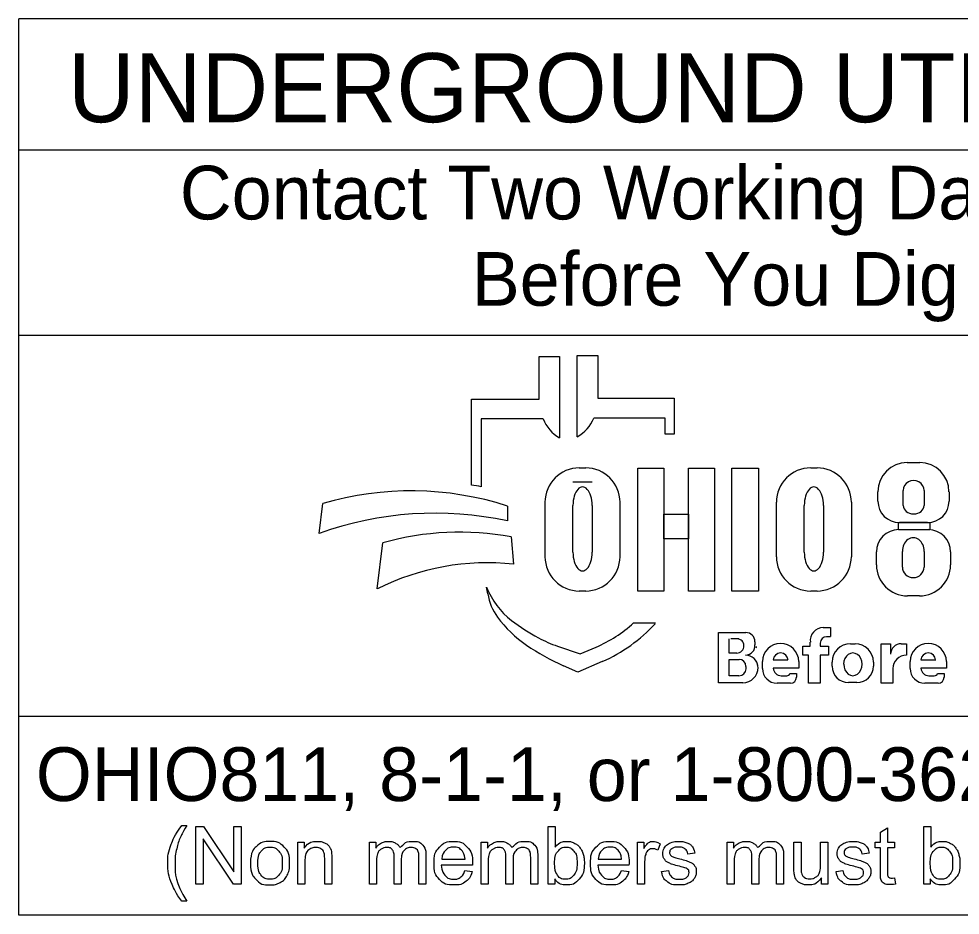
# Model space of a CAD drawing. Extents: x 0 to 34, y 0 to 22.
# Drawn here: x 2.378 to 4.831, y 2.661 to 4.999 of the extents above; entities that cross this region are included whole.
import ezdxf

# ---------------------------------------------------------------- set-up
doc = ezdxf.new("R2010")
doc.units = 0
doc.layers.add('SH_Data', color=7, linetype='Continuous')
doc.layers.add('SH_Text', color=7, linetype='Continuous')

msp = doc.modelspace()

# ---------------------------------------------------------------- linework, layer by layer
at = {"layer": 'SH_Data'}
for p, q in [((2.3775, 2.6613), (2.3775, 4.9988)), ((6.6275, 4.9988), (2.3775, 4.9988)), ((2.3775, 4.6573), (6.6275, 4.6573)), ((2.3775, 4.1739), (6.6275, 4.1739)), ((6.6275, 3.1792), (2.3775, 3.1792)), ((6.6275, 2.6613), (2.3775, 2.6613))]:
    msp.add_line(p, q, dxfattribs=at)
at = {"layer": 'SH_Text'}
for p, q in [((3.7335, 4.0068), (3.7335, 4.1183)), ((3.7335, 4.1183), (3.7872, 4.1183)), ((3.7872, 4.1183), (3.7872, 3.9062)), ((3.8329, 3.9086), (3.8329, 4.1206)), ((3.8329, 4.1206), (3.8865, 4.1206)), ((3.8865, 4.1206), (3.8865, 4.0092)), ((3.5576, 3.7829), (3.5576, 4.0068)), ((3.5576, 4.0068), (3.7335, 4.0068)), ((3.8865, 4.0092), (4.0857, 4.0092)), ((4.0857, 4.0092), (4.0857, 3.9153)), ((3.5828, 3.9554), (3.5828, 3.7785)), ((3.7439, 3.9554), (3.5828, 3.9554)), ((4.0625, 3.9577), (3.8761, 3.9577)), ((4.0625, 3.9153), (4.0625, 3.9577)), ((4.0857, 3.9153), (4.0625, 3.9153)), ((4.6931, 3.8416), (4.7258, 3.8416)), ((3.8385, 3.8276), (3.8551, 3.8276)), ((4.4416, 3.8276), (4.4581, 3.8276)), ((3.8718, 3.7906), (3.822, 3.7906)), ((4.6168, 3.741), (4.6168, 3.7653)), ((4.683, 3.7297), (4.683, 3.7689)), ((4.7371, 3.7689), (4.7371, 3.7297)), ((4.8022, 3.7653), (4.8022, 3.741)), ((3.1602, 3.6566), (3.1696, 3.7348)), ((3.7491, 3.5962), (3.7491, 3.7382)), ((3.822, 3.6076), (3.822, 3.7299)), ((3.8718, 3.7299), (3.8718, 3.6076)), ((3.9445, 3.7382), (3.9445, 3.5962)), ((4.3521, 3.5962), (4.3521, 3.7382)), ((4.425, 3.6076), (4.425, 3.7299)), ((4.4748, 3.7299), (4.4748, 3.6076)), ((4.5476, 3.7382), (4.5476, 3.5962)), ((3.6509, 3.7283), (3.6509, 3.6894)), ((4.7462, 3.685), (4.6728, 3.685)), ((4.671, 3.6667), (4.7483, 3.6667)), ((3.312, 3.5121), (3.3267, 3.6322)), ((3.6608, 3.6477), (3.6671, 3.5767)), ((4.6131, 3.5748), (4.6131, 3.6088)), ((4.6806, 3.5689), (4.6806, 3.6098)), ((4.7374, 3.6098), (4.7374, 3.5689)), ((4.8062, 3.6088), (4.8062, 3.5748)), ((3.5997, 3.4992), (3.5967, 3.5171)), ((3.8551, 3.5067), (3.8385, 3.5067)), ((4.4581, 3.5067), (4.4416, 3.5067)), ((4.7252, 3.4939), (4.6941, 3.4939)), ((3.98, 3.4233), (4.0375, 3.4233)), ((4.4739, 3.4111), (4.4934, 3.4111)), ((4.4934, 3.4111), (4.4934, 3.3881)), ((4.2013, 3.2676), (4.2013, 3.3983)), ((4.2013, 3.3983), (4.2725, 3.3983)), ((4.4934, 3.3876), (4.4832, 3.3876)), ((3.7816, 3.363), (3.841, 3.3425)), ((4.2293, 3.3448), (4.2293, 3.3818)), ((4.2545, 3.3818), (4.2332, 3.3818)), ((4.2963, 3.3745), (4.2963, 3.3666)), ((4.4213, 3.3397), (4.4213, 3.3627)), ((4.4213, 3.3627), (4.4406, 3.3627)), ((4.4406, 3.3627), (4.4406, 3.3732)), ((4.4667, 3.3711), (4.4667, 3.3627)), ((4.4667, 3.3627), (4.4883, 3.3627)), ((4.4883, 3.3627), (4.4883, 3.3397)), ((4.5451, 3.3693), (4.5573, 3.3693)), ((4.6254, 3.2664), (4.6254, 3.3691)), ((4.6254, 3.3691), (4.6499, 3.3691)), ((4.6499, 3.3691), (4.6499, 3.3422)), ((4.6772, 3.3691), (4.691, 3.3691)), ((4.691, 3.3691), (4.691, 3.3394)), ((3.841, 3.3425), (3.8821, 3.3603)), ((4.2487, 3.3448), (4.2293, 3.3448)), ((4.4362, 3.3397), (4.4213, 3.3397)), ((4.4362, 3.2664), (4.4362, 3.3397)), ((4.4883, 3.3397), (4.4667, 3.3397)), ((4.4667, 3.3397), (4.4667, 3.2664)), ((3.8983, 3.3229), (3.835, 3.2954)), ((4.2293, 3.2854), (4.2293, 3.3283)), ((4.2293, 3.3283), (4.2548, 3.3283)), ((4.3159, 3.3044), (4.3159, 3.3228)), ((4.3824, 3.3267), (4.3439, 3.3267)), ((4.4104, 3.3228), (4.4104, 3.3051)), ((4.4973, 3.3107), (4.4973, 3.3215)), ((4.6051, 3.3215), (4.6051, 3.3107)), ((4.7008, 3.3044), (4.7008, 3.3228)), ((4.7674, 3.3267), (4.7288, 3.3267)), ((4.7953, 3.3228), (4.7953, 3.3051)), ((3.835, 3.2954), (3.7976, 3.3119)), ((4.2729, 3.3102), (4.2729, 3.3038)), ((4.3043, 3.3072), (4.3043, 3.3069)), ((4.4104, 3.3051), (4.344, 3.3051)), ((4.3876, 3.2914), (4.4045, 3.2914)), ((4.4045, 3.2914), (4.4045, 3.2816)), ((4.6559, 3.3045), (4.6559, 3.2664)), ((4.7953, 3.3051), (4.7289, 3.3051)), ((4.7725, 3.2914), (4.7894, 3.2914)), ((4.7894, 3.2914), (4.7894, 3.2816)), ((4.265, 3.2676), (4.2013, 3.2676)), ((4.2546, 3.2854), (4.2293, 3.2854)), ((4.3892, 3.2664), (4.3538, 3.2664)), ((4.3649, 3.2859), (4.379, 3.2859)), ((4.4667, 3.2664), (4.4362, 3.2664)), ((4.5623, 3.2679), (4.5401, 3.2679)), ((4.6559, 3.2664), (4.6254, 3.2664)), ((4.7742, 3.2664), (4.7388, 3.2664)), ((4.7498, 3.2859), (4.7639, 3.2859))]:
    msp.add_line(p, q, dxfattribs=at)
for points in [[(3.991, 3.8266), (4.0589, 3.8266), (4.0589, 3.5066), (3.991, 3.5066)], [(4.1231, 3.8266), (4.1911, 3.8266), (4.1911, 3.5066), (4.1231, 3.5066)], [(4.2364, 3.8266), (4.3052, 3.8266), (4.3052, 3.5066), (4.2364, 3.5066)], [(4.0589, 3.7067), (4.1231, 3.7067), (4.1231, 3.6427), (4.0589, 3.6427)], [(4.6706, 3.6851), (4.7523, 3.6851), (4.7523, 3.6666), (4.6706, 3.6666)]]:
    msp.add_lwpolyline(points, close=True, dxfattribs=at)
for points in [[(2.8021, 2.8951), (2.8153, 2.8951)], [(2.8389, 2.7425), (2.8389, 2.8926), (2.8592, 2.8926), (2.9382, 2.7747), (2.9382, 2.8926), (2.9572, 2.8926), (2.9572, 2.7425), (2.9369, 2.7425), (2.8579, 2.8604), (2.8579, 2.7425), (2.8389, 2.7425)], [(3.7743, 2.7425), (3.7573, 2.7425), (3.7573, 2.8926), (3.7757, 2.8926), (3.7757, 2.8391)], [(4.6233, 2.7743), (4.6233, 2.837), (4.6097, 2.837), (4.6097, 2.8513), (4.6233, 2.8513), (4.6233, 2.8782), (4.6417, 2.8893), (4.6417, 2.8513), (4.6601, 2.8513), (4.6601, 2.837), (4.6417, 2.837), (4.6417, 2.7732)], [(4.7534, 2.7425), (4.7363, 2.7425), (4.7363, 2.8926), (4.7548, 2.8926), (4.7548, 2.8391)], [(3.1048, 2.7425), (3.1048, 2.8513), (3.1214, 2.8513), (3.1214, 2.8358)], [(3.2912, 2.7425), (3.2912, 2.8513), (3.3077, 2.8513), (3.3077, 2.8359)], [(3.5826, 2.7425), (3.5826, 2.8513), (3.5991, 2.8513), (3.5991, 2.8359)], [(3.9904, 2.7425), (3.9904, 2.8513), (4.007, 2.8513), (4.007, 2.8348)], [(4.0495, 2.8478), (4.043, 2.8307)], [(4.2236, 2.7425), (4.2236, 2.8513), (4.2401, 2.8513), (4.2401, 2.8359)], [(4.3979, 2.7839), (4.3979, 2.8513), (4.4164, 2.8513), (4.4164, 2.791)], [(4.4676, 2.793), (4.4676, 2.8513), (4.4861, 2.8513), (4.4861, 2.7425), (4.4696, 2.7425)], [(4.1394, 2.8231), (4.1213, 2.8207)], [(4.594, 2.8231), (4.5759, 2.8207)], [(3.1233, 2.8018), (3.1233, 2.7425), (3.1048, 2.7425)], [(3.1932, 2.8093), (3.1932, 2.7425), (3.1748, 2.7425), (3.1748, 2.8086)], [(3.3097, 2.7989), (3.3097, 2.7425), (3.2912, 2.7425)], [(3.3743, 2.8056), (3.3743, 2.7425), (3.3559, 2.7425), (3.3559, 2.8131)], [(3.4388, 2.8171), (3.4388, 2.7425), (3.4203, 2.7425), (3.4203, 2.811)], [(3.4799, 2.8072), (3.5406, 2.8072)], [(3.601, 2.7989), (3.601, 2.7425), (3.5826, 2.7425)], [(3.6657, 2.8056), (3.6657, 2.7425), (3.6473, 2.7425), (3.6473, 2.8131)], [(3.7301, 2.8171), (3.7301, 2.7425), (3.7117, 2.7425), (3.7117, 2.811)], [(3.8879, 2.8072), (3.9486, 2.8072)], [(4.0088, 2.7994), (4.0088, 2.7425), (3.9904, 2.7425)], [(4.242, 2.7989), (4.242, 2.7425), (4.2236, 2.7425)], [(4.3067, 2.8056), (4.3067, 2.7425), (4.2883, 2.7425), (4.2883, 2.8131)], [(4.3711, 2.8171), (4.3711, 2.7425), (4.3527, 2.7425), (4.3527, 2.811)], [(3.56, 2.7921), (3.4788, 2.7921)], [(3.5404, 2.7776), (3.5595, 2.7752)], [(3.968, 2.7921), (3.8868, 2.7921)], [(3.9484, 2.7776), (3.9675, 2.7752)], [(4.053, 2.775), (4.0712, 2.7778)], [(4.5076, 2.775), (4.5258, 2.7778)], [(3.7743, 2.7561), (3.7743, 2.7425)], [(4.4696, 2.7425), (4.4696, 2.7585)], [(4.6601, 2.7589), (4.6628, 2.7426)], [(4.7534, 2.7561), (4.7534, 2.7425)], [(2.8153, 2.6983), (2.8021, 2.6983)]]:
    msp.add_lwpolyline(points, dxfattribs=at)
for centre, radius, start, end in [((3.8353, 3.9922), 0.0985, 201.9296, 240.7469), ((3.7847, 3.9945), 0.0985, 299.2531, 338.0704), ((4.6931, 3.7653), 0.0763, 90, 180), ((4.7258, 3.7653), 0.0763, 0, 90), ((3.8385, 3.7382), 0.0895, 90, 180), ((3.8551, 3.7382), 0.0895, 0, 90), ((4.4416, 3.7382), 0.0895, 90, 180), ((4.4581, 3.7382), 0.0895, 0, 90), ((3.4295, 2.974), 0.8191, 79.2074, 81.0007), ((3.3997, 2.9487), 0.8191, 72.1402, 106.3144), ((4.6728, 3.741), 0.056, 180, 270), ((4.7462, 3.741), 0.056, 270, 0), ((3.4628, 2.8176), 0.8919, 77.8238, 109.8274), ((3.5267, 2.9279), 0.7322, 79.44, 105.8467), ((4.671, 3.6088), 0.0579, 90, 180), ((4.7483, 3.6088), 0.0579, 0, 90), ((3.8385, 3.5962), 0.0895, 180, 270), ((3.8551, 3.5962), 0.0895, 270, 0), ((4.4416, 3.5962), 0.0895, 180, 270), ((4.4581, 3.5962), 0.0895, 270, 0), ((3.5987, 2.9447), 0.6357, 83.8248, 116.8021), ((4.6941, 3.5748), 0.081, 180, 270), ((4.7252, 3.5748), 0.081, 270, 0), ((3.7841, 3.5892), 0.2008, 201.0457, 232.5314), ((3.741, 3.5233), 0.1433, 189.6817, 216.0884), ((3.8747, 3.6207), 0.3088, 216.0884, 235.7167), ((3.9766, 3.8405), 0.5173, 232.5314, 241.794), ((3.7387, 3.6907), 0.3602, 293.4582, 312.0712), ((3.7387, 3.6907), 0.401, 293.4582, 317.8286), ((4.4739, 3.3776), 0.0335, 90, 187.5187), ((4.2725, 3.3745), 0.0238, 0, 90), ((4.4832, 3.3711), 0.0165, 90, 180), ((4.0412, 3.865), 0.6044, 235.7167, 246.2325), ((3.8914, 3.6816), 0.3371, 241.794, 250.9821), ((4.2487, 3.3636), 0.0187, 270, 2.0582), ((4.2505, 3.3649), 0.0169, 357.8325, 90), ((4.2721, 3.3638), 0.0243, 270, 6.6529), ((4.2827, 3.3623), 0.0175, 347.4023, 0), ((4.3631, 3.3228), 0.0473, 0, 180), ((4.5451, 3.3215), 0.0478, 90, 180), ((4.5573, 3.3215), 0.0478, 0, 90), ((4.6768, 3.3422), 0.0269, 89.2449, 180), ((4.7481, 3.3228), 0.0473, 0, 180), ((4.2722, 3.3074), 0.0321, 4.0748, 90), ((4.3632, 3.3258), 0.0193, 2.9632, 177.0368), ((4.6908, 3.3045), 0.0349, 89.6033, 180), ((4.7481, 3.3258), 0.0193, 2.9632, 177.0368), ((4.2548, 3.3102), 0.0181, 0, 90), ((4.2714, 3.3072), 0.033, 0, 11.7502), ((4.2546, 3.3038), 0.0184, 270, 0), ((4.265, 3.3069), 0.0393, 270, 0), ((4.3538, 3.3044), 0.038, 180, 270), ((4.3649, 3.3069), 0.021, 184.827, 270), ((4.379, 3.2952), 0.00938, 270, 335.9979), ((4.5401, 3.3107), 0.0428, 180, 270), ((4.5623, 3.3107), 0.0428, 270, 0), ((4.7388, 3.3044), 0.038, 180, 270), ((4.7498, 3.3069), 0.021, 184.827, 270), ((4.7639, 3.2952), 0.00938, 270, 335.9979), ((4.3892, 3.2816), 0.0152, 270, 0), ((4.7742, 3.2816), 0.0152, 270, 0)]:
    msp.add_arc(centre, radius, start, end, dxfattribs=at)
for centre, major_axis, ratio, start_param, end_param in [((4.71, 3.7689), (0.0271, 0), 0.969373, 0, 3.141593), ((3.8469, 3.7299), (0, 0.0484), 0.514403, 4.712389, 7.853982), ((4.4499, 3.7299), (0, 0.0484), 0.514403, 4.712389, 7.853982), ((4.71, 3.7297), (0.0271, 0), 0.818453, 3.141593, 6.283185), ((4.709, 3.6098), (0, 0.0358), 0.794529, 4.712389, 7.853982), ((3.8469, 3.6076), (0, 0.0484), 0.514403, 1.570796, 4.712389), ((4.4499, 3.6076), (0, 0.0484), 0.514403, 1.570796, 4.712389), ((4.709, 3.5689), (0.0284, 0), 0.959837, 3.141593, 6.283185), ((4.5517, 3.3161), (0, 0.029), 0.832186, 4.712389, 7.853982), ((4.5517, 3.3161), (0, 0.0302), 0.797287, 1.570796, 4.712389)]:
    msp.add_ellipse(centre, major_axis=major_axis, ratio=ratio, start_param=start_param, end_param=end_param, dxfattribs=at)
for points in [[(2.8021, 2.6983), (2.7869, 2.7175), (2.7763, 2.7433), (2.7657, 2.7692), (2.7657, 2.7968), (2.7657, 2.8212), (2.7736, 2.8435), (2.7829, 2.8694), (2.8021, 2.8951)], [(2.8153, 2.8951), (2.8029, 2.8738), (2.7989, 2.8647), (2.7927, 2.8506), (2.7891, 2.8352), (2.7847, 2.8161), (2.7847, 2.7967), (2.7847, 2.7474), (2.8153, 2.6983)], [(2.9814, 2.7969), (2.9814, 2.8271), (2.9981, 2.8416), (3.0122, 2.8537), (3.0323, 2.8537), (3.0547, 2.8537), (3.069, 2.839), (3.0832, 2.8243), (3.0832, 2.7984), (3.0832, 2.7774), (3.0769, 2.7654), (3.0706, 2.7534), (3.0586, 2.7467), (3.0466, 2.7401), (3.0323, 2.7401), (3.0095, 2.7401), (2.9954, 2.7547), (2.9814, 2.7693), (2.9814, 2.7969)], [(3.1214, 2.8358), (3.1334, 2.8537), (3.156, 2.8537), (3.1659, 2.8537), (3.1741, 2.8502), (3.1823, 2.8466), (3.1864, 2.8409), (3.1905, 2.8352), (3.1922, 2.8273), (3.1932, 2.8221), (3.1932, 2.8093)], [(3.3077, 2.8359), (3.3128, 2.8439), (3.3214, 2.8488), (3.3299, 2.8537), (3.3407, 2.8537), (3.3528, 2.8537), (3.3606, 2.8487), (3.3683, 2.8436), (3.3715, 2.8346), (3.3844, 2.8537), (3.4051, 2.8537), (3.4213, 2.8537), (3.43, 2.8447), (3.4388, 2.8358), (3.4388, 2.8171)], [(3.5595, 2.7752), (3.555, 2.7585), (3.5428, 2.7493), (3.5306, 2.7401), (3.5117, 2.7401), (3.4878, 2.7401), (3.4738, 2.7547), (3.4598, 2.7694), (3.4598, 2.796), (3.4598, 2.8234), (3.474, 2.8385), (3.4881, 2.8537), (3.5106, 2.8537), (3.5324, 2.8537), (3.5463, 2.8388), (3.5601, 2.824), (3.5601, 2.797), (3.5601, 2.7954), (3.56, 2.7921)], [(3.5991, 2.8359), (3.6042, 2.8439), (3.6127, 2.8488), (3.6212, 2.8537), (3.6321, 2.8537), (3.6442, 2.8537), (3.6519, 2.8487), (3.6597, 2.8436), (3.6628, 2.8346), (3.6758, 2.8537), (3.6965, 2.8537), (3.7127, 2.8537), (3.7214, 2.8447), (3.7301, 2.8358), (3.7301, 2.8171)], [(3.7757, 2.8391), (3.7874, 2.8537), (3.8055, 2.8537), (3.8155, 2.8537), (3.8245, 2.8497), (3.8335, 2.8456), (3.8392, 2.8383), (3.845, 2.831), (3.8483, 2.8206), (3.8516, 2.8103), (3.8516, 2.7985), (3.8516, 2.7706), (3.8378, 2.7553), (3.8239, 2.7401), (3.8046, 2.7401), (3.7853, 2.7401), (3.7743, 2.7561)], [(3.9675, 2.7752), (3.963, 2.7585), (3.9508, 2.7493), (3.9386, 2.7401), (3.9196, 2.7401), (3.8958, 2.7401), (3.8818, 2.7547), (3.8678, 2.7694), (3.8678, 2.796), (3.8678, 2.8234), (3.882, 2.8385), (3.8961, 2.8537), (3.9186, 2.8537), (3.9404, 2.8537), (3.9543, 2.8388), (3.9681, 2.824), (3.9681, 2.797), (3.9681, 2.7954), (3.968, 2.7921)], [(4.007, 2.8348), (4.0133, 2.8463), (4.0187, 2.85), (4.0241, 2.8537), (4.0305, 2.8537), (4.0398, 2.8537), (4.0495, 2.8478)], [(4.0712, 2.7778), (4.0727, 2.7668), (4.0798, 2.761), (4.0868, 2.7552), (4.0995, 2.7552), (4.1122, 2.7552), (4.1184, 2.7603), (4.1245, 2.7655), (4.1245, 2.7725), (4.1245, 2.7788), (4.1191, 2.7823), (4.1153, 2.7848), (4.1002, 2.7886), (4.0799, 2.7937), (4.072, 2.7975), (4.0642, 2.8012), (4.0601, 2.8078), (4.0561, 2.8144), (4.0561, 2.8224), (4.0561, 2.8296), (4.0594, 2.8358), (4.0628, 2.842), (4.0685, 2.8461), (4.0728, 2.8493), (4.0803, 2.8515), (4.0877, 2.8537), (4.0962, 2.8537), (4.109, 2.8537), (4.1187, 2.85), (4.1284, 2.8463), (4.133, 2.84), (4.1377, 2.8337), (4.1394, 2.8231)], [(4.2401, 2.8359), (4.2452, 2.8439), (4.2537, 2.8488), (4.2622, 2.8537), (4.2731, 2.8537), (4.2852, 2.8537), (4.2929, 2.8487), (4.3007, 2.8436), (4.3038, 2.8346), (4.3168, 2.8537), (4.3375, 2.8537), (4.3537, 2.8537), (4.3624, 2.8447), (4.3711, 2.8358), (4.3711, 2.8171)], [(4.5258, 2.7778), (4.5273, 2.7668), (4.5343, 2.761), (4.5414, 2.7552), (4.554, 2.7552), (4.5668, 2.7552), (4.5729, 2.7603), (4.5791, 2.7655), (4.5791, 2.7725), (4.5791, 2.7788), (4.5736, 2.7823), (4.5698, 2.7848), (4.5548, 2.7886), (4.5345, 2.7937), (4.5266, 2.7975), (4.5188, 2.8012), (4.5147, 2.8078), (4.5107, 2.8144), (4.5107, 2.8224), (4.5107, 2.8296), (4.514, 2.8358), (4.5173, 2.842), (4.5231, 2.8461), (4.5274, 2.8493), (4.5348, 2.8515), (4.5423, 2.8537), (4.5508, 2.8537), (4.5636, 2.8537), (4.5733, 2.85), (4.583, 2.8463), (4.5876, 2.84), (4.5922, 2.8337), (4.594, 2.8231)], [(4.7548, 2.8391), (4.7664, 2.8537), (4.7846, 2.8537), (4.7946, 2.8537), (4.8036, 2.8497), (4.8125, 2.8456), (4.8183, 2.8383), (4.8241, 2.831), (4.8274, 2.8206), (4.8306, 2.8103), (4.8306, 2.7985), (4.8306, 2.7706), (4.8168, 2.7553), (4.803, 2.7401), (4.7836, 2.7401), (4.7644, 2.7401), (4.7534, 2.7561)], [(3.0003, 2.7969), (3.0003, 2.776), (3.0094, 2.7656), (3.0185, 2.7552), (3.0323, 2.7552), (3.046, 2.7552), (3.0551, 2.7656), (3.0642, 2.7761), (3.0642, 2.7975), (3.0642, 2.8177), (3.0551, 2.8281), (3.0459, 2.8385), (3.0323, 2.8385), (3.0185, 2.8385), (3.0094, 2.8281), (3.0003, 2.8178), (3.0003, 2.7969)], [(3.1748, 2.8086), (3.1748, 2.8199), (3.1726, 2.8254), (3.1705, 2.831), (3.165, 2.8343), (3.1595, 2.8377), (3.1521, 2.8377), (3.1404, 2.8377), (3.1318, 2.8302), (3.1233, 2.8227), (3.1233, 2.8018)], [(3.3559, 2.8131), (3.3559, 2.8254), (3.3514, 2.8315), (3.3469, 2.8377), (3.3366, 2.8377), (3.3288, 2.8377), (3.3222, 2.8336), (3.3156, 2.8295), (3.3126, 2.8216), (3.3097, 2.8137), (3.3097, 2.7989)], [(3.4203, 2.811), (3.4203, 2.822), (3.4185, 2.8269), (3.4168, 2.8317), (3.412, 2.8347), (3.4073, 2.8377), (3.401, 2.8377), (3.3895, 2.8377), (3.3819, 2.83), (3.3743, 2.8224), (3.3743, 2.8056)], [(3.5406, 2.8072), (3.5394, 2.821), (3.5337, 2.8279), (3.5249, 2.8386), (3.5108, 2.8386), (3.4981, 2.8386), (3.4894, 2.8301), (3.4808, 2.8215), (3.4799, 2.8072)], [(3.6473, 2.8131), (3.6473, 2.8254), (3.6428, 2.8315), (3.6383, 2.8377), (3.628, 2.8377), (3.6202, 2.8377), (3.6136, 2.8336), (3.607, 2.8295), (3.604, 2.8216), (3.601, 2.8137), (3.601, 2.7989)], [(3.7117, 2.811), (3.7117, 2.822), (3.7099, 2.8269), (3.7081, 2.8317), (3.7034, 2.8347), (3.6987, 2.8377), (3.6923, 2.8377), (3.6809, 2.8377), (3.6733, 2.83), (3.6657, 2.8224), (3.6657, 2.8056)], [(3.7741, 2.7977), (3.7741, 2.7781), (3.7794, 2.7694), (3.7881, 2.7552), (3.8029, 2.7552), (3.815, 2.7552), (3.8238, 2.7657), (3.8326, 2.7762), (3.8326, 2.797), (3.8326, 2.8183), (3.8241, 2.8284), (3.8157, 2.8386), (3.8038, 2.8386), (3.7917, 2.8386), (3.7829, 2.8281), (3.7741, 2.8176), (3.7741, 2.7977)], [(3.9486, 2.8072), (3.9474, 2.821), (3.9417, 2.8279), (3.9328, 2.8386), (3.9188, 2.8386), (3.9061, 2.8386), (3.8974, 2.8301), (3.8888, 2.8215), (3.8879, 2.8072)], [(4.043, 2.8307), (4.0363, 2.8347), (4.0295, 2.8347), (4.0235, 2.8347), (4.0187, 2.8311), (4.0139, 2.8274), (4.0119, 2.821), (4.0088, 2.8111), (4.0088, 2.7994)], [(4.1213, 2.8207), (4.1201, 2.8291), (4.1142, 2.8339), (4.1083, 2.8386), (4.0975, 2.8386), (4.0848, 2.8386), (4.0794, 2.8344), (4.0739, 2.8302), (4.0739, 2.8245), (4.0739, 2.8209), (4.0762, 2.8181), (4.0785, 2.8151), (4.0833, 2.8131), (4.086, 2.8121), (4.0996, 2.8084), (4.1192, 2.8032), (4.1269, 2.7999), (4.1347, 2.7966), (4.1391, 2.7902), (4.1435, 2.7839), (4.1435, 2.7744), (4.1435, 2.7652), (4.1381, 2.7571), (4.1327, 2.749), (4.1226, 2.7445), (4.1124, 2.7401), (4.0996, 2.7401), (4.0784, 2.7401), (4.0672, 2.7489), (4.0561, 2.7577), (4.053, 2.775)], [(4.2883, 2.8131), (4.2883, 2.8254), (4.2838, 2.8315), (4.2793, 2.8377), (4.269, 2.8377), (4.2612, 2.8377), (4.2546, 2.8336), (4.248, 2.8295), (4.245, 2.8216), (4.242, 2.8137), (4.242, 2.7989)], [(4.3527, 2.811), (4.3527, 2.822), (4.3509, 2.8269), (4.3491, 2.8317), (4.3444, 2.8347), (4.3397, 2.8377), (4.3333, 2.8377), (4.3219, 2.8377), (4.3143, 2.83), (4.3067, 2.8224), (4.3067, 2.8056)], [(4.5759, 2.8207), (4.5747, 2.8291), (4.5688, 2.8339), (4.5629, 2.8386), (4.5521, 2.8386), (4.5394, 2.8386), (4.5339, 2.8344), (4.5285, 2.8302), (4.5285, 2.8245), (4.5285, 2.8209), (4.5308, 2.8181), (4.533, 2.8151), (4.5378, 2.8131), (4.5406, 2.8121), (4.5542, 2.8084), (4.5737, 2.8032), (4.5815, 2.7999), (4.5893, 2.7966), (4.5937, 2.7902), (4.5981, 2.7839), (4.5981, 2.7744), (4.5981, 2.7652), (4.5927, 2.7571), (4.5873, 2.749), (4.5772, 2.7445), (4.567, 2.7401), (4.5542, 2.7401), (4.5329, 2.7401), (4.5218, 2.7489), (4.5107, 2.7577), (4.5076, 2.775)], [(4.7532, 2.7977), (4.7532, 2.7781), (4.7585, 2.7694), (4.7672, 2.7552), (4.782, 2.7552), (4.7941, 2.7552), (4.8029, 2.7657), (4.8116, 2.7762), (4.8116, 2.797), (4.8116, 2.8183), (4.8032, 2.8284), (4.7948, 2.8386), (4.7828, 2.8386), (4.7708, 2.8386), (4.762, 2.8281), (4.7532, 2.8176), (4.7532, 2.7977)], [(3.4788, 2.7921), (3.4799, 2.7742), (3.489, 2.7647), (3.4981, 2.7552), (3.5117, 2.7552), (3.5219, 2.7552), (3.5291, 2.7605), (3.5362, 2.7659), (3.5404, 2.7776)], [(3.8868, 2.7921), (3.8879, 2.7742), (3.897, 2.7647), (3.9061, 2.7552), (3.9197, 2.7552), (3.9299, 2.7552), (3.937, 2.7605), (3.9442, 2.7659), (3.9484, 2.7776)], [(4.4696, 2.7585), (4.4569, 2.7401), (4.4351, 2.7401), (4.4255, 2.7401), (4.4171, 2.7437), (4.4088, 2.7474), (4.4047, 2.753), (4.4007, 2.7586), (4.3991, 2.7667), (4.3979, 2.7721), (4.3979, 2.7839)], [(4.4164, 2.791), (4.4164, 2.7765), (4.4175, 2.7715), (4.4192, 2.7643), (4.4249, 2.7601), (4.4305, 2.756), (4.4388, 2.756), (4.4471, 2.756), (4.4543, 2.7602), (4.4616, 2.7645), (4.4646, 2.7718), (4.4676, 2.7791), (4.4676, 2.793)], [(4.6628, 2.7426), (4.655, 2.741), (4.6488, 2.741), (4.6388, 2.741), (4.6333, 2.7441), (4.6278, 2.7473), (4.6255, 2.7525), (4.6233, 2.7577), (4.6233, 2.7743)], [(4.6417, 2.7732), (4.6417, 2.7653), (4.6427, 2.7631), (4.6436, 2.7608), (4.6458, 2.7595), (4.648, 2.7581), (4.6521, 2.7581), (4.6551, 2.7581), (4.6601, 2.7589)]]:
    msp.add_open_spline(points, degree=3, dxfattribs=at)

# ---------------------------------------------------------------- texts
for s, height, p in [('UNDERGROUND UTILITIES', 0.18, (2.5057, 4.7292)), ('Contact Two Working Days', 0.14, (2.7972, 4.4757)), ('Before You Dig', 0.14, (3.5583, 4.2507)), ('OHIO811, 8-1-1, or 1-800-362-2764', 0.14, (2.422, 2.9591))]:
    msp.add_text(s, height=height, dxfattribs=at).set_placement(p)

doc.saveas('drawing.dxf')
